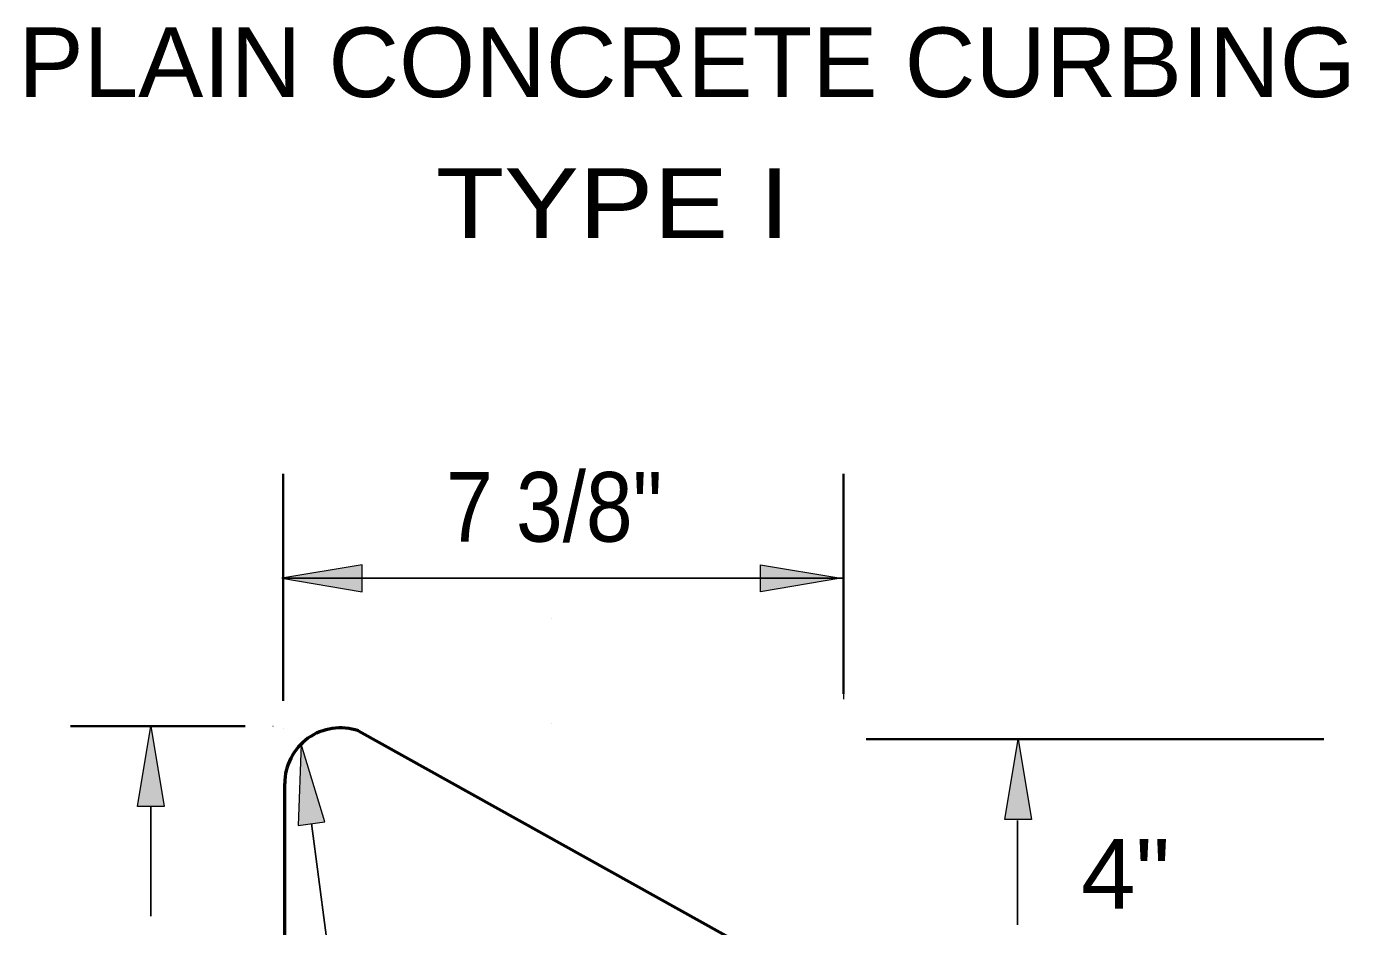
# Model space of a CAD drawing. Extents: x 36.6 to 71.9, y 0.8 to 22.8.
# Drawn here: x 55.33 to 58.293, y 14.457 to 16.476 of the extents above; entities that cross this region are included whole.
import ezdxf

# ---------------------------------------------------------------- set-up
doc = ezdxf.new("R2010")
doc.units = 0
doc.header["$LTSCALE"] = 0.062
for name, color, linetype, lineweight in [('1', 7, 'Continuous', 13), ('3', 7, 'Continuous', 25), ('8', 7, 'Continuous', 13)]:
    doc.layers.add(name, color=color, linetype=linetype, lineweight=lineweight)

msp = doc.modelspace()

# ---------------------------------------------------------------- hatches: boundary and pattern name
at = {"layer": '1'}
for points in [[(56.08267, 15.20792), (56.08267, 15.26792), (55.90258, 15.23792), (55.90258, 15.23792)], [(56.97508, 15.20792), (56.97508, 15.26792), (57.15508, 15.23792), (57.15508, 15.23792)], [(55.63867, 14.72633), (55.57867, 14.72633), (55.60858, 14.90633), (55.60858, 14.90633)], [(57.58267, 14.69683), (57.52267, 14.69683), (57.55267, 14.87683), (57.55267, 14.87683)]]:
    msp.add_hatch(color=256, dxfattribs=at).paths.add_polyline_path(points)
at = {"layer": '3'}
msp.add_hatch(color=256, dxfattribs=at).paths.add_polyline_path([(55.93925, 14.68383), (55.99883, 14.69167), (55.94575, 14.86625), (55.94575, 14.86625)])

# ---------------------------------------------------------------- linework, layer by layer
at = {"layer": '1', "lineweight": 35}
for p, q in [((55.9055, 14.96308), (55.9055, 15.47192)), ((57.16108, 14.97875), (57.16108, 15.47192)), ((55.82008, 14.90633), (55.42867, 14.90633)), ((57.21225, 14.87725), (58.23817, 14.87725))]:
    msp.add_line(p, q, dxfattribs=at)
at = {"layer": '1'}
for p, q in [((55.9055, 15.02558), (55.9055, 15.32692)), ((57.16108, 15.08442), (57.16108, 14.96692))]:
    msp.add_line(p, q, dxfattribs=at)
at = {"layer": '1', "lineweight": 25}
for p, q in [((57.15808, 15.23792), (55.9025, 15.23792)), ((55.60867, 14.48058), (55.60867, 14.72633)), ((57.55117, 14.69517), (57.55117, 14.46067))]:
    msp.add_line(p, q, dxfattribs=at)
at = {"layer": '1', "lineweight": 53}
for p, q in [((56.074, 14.89583), (57.09425, 14.3275)), ((55.90883, 11.51508), (55.90883, 14.7775))]:
    msp.add_line(p, q, dxfattribs=at)
at = {"layer": '1'}
for points in [[(56.08267, 15.20792), (56.08267, 15.26792), (55.90258, 15.23792), (55.90258, 15.23792)], [(56.97508, 15.20792), (56.97508, 15.26792), (57.15508, 15.23792), (57.15508, 15.23792)], [(55.63867, 14.72633), (55.57867, 14.72633), (55.60858, 14.90633), (55.60858, 14.90633)], [(57.58267, 14.69683), (57.52267, 14.69683), (57.55267, 14.87683), (57.55267, 14.87683)]]:
    msp.add_lwpolyline(points, close=True, dxfattribs=at)
at = {"layer": '1', "lineweight": 53}
msp.add_arc((56.03383, 14.7775), 0.125, 71.23187, 180, dxfattribs=at)
at = {"layer": '3', "lineweight": 13}
msp.add_lwpolyline([(55.93925, 14.68383), (55.99883, 14.69167), (55.94575, 14.86625), (55.94575, 14.86625)], close=True, dxfattribs=at)
at = {"layer": '3'}
msp.add_lwpolyline([(55.96908, 14.68775), (56.03158, 14.20958), (56.36908, 13.96008)], dxfattribs=at)
at = {"layer": '8'}
for p, q in [((57.16108, 15.45325), (57.16117, 15.45325)), ((55.9055, 15.14692), (55.90558, 15.14692)), ((56.50625, 15.14692), (56.50633, 15.14692)), ((57.16108, 15.14692), (57.16117, 15.14692)), ((57.16108, 15.14692), (57.16117, 15.14692)), ((55.9055, 14.96308), (55.90558, 14.96308)), ((55.60867, 14.90633), (55.60875, 14.90633)), ((55.88258, 14.90633), (55.88267, 14.90633)), ((56.50625, 14.91258), (56.50633, 14.91258)), ((55.9055, 14.90058), (55.90558, 14.90058))]:
    msp.add_line(p, q, dxfattribs=at)

# ---------------------------------------------------------------- texts
at = {"layer": '1'}
for s, width, p in [('7 3/8"', 0.9, (56.27058, 15.32008)), ('4"', 1.05, (57.69367, 14.49717))]:
    msp.add_text(s, height=0.1562, dxfattribs=dict(at, width=width)).set_placement(p)
at = {"layer": '3'}
for s, width, p in [('PLAIN CONCRETE CURBING', 1.05, (55.312, 16.31708)), ('TYPE I', 1.2, (56.24775, 16.001))]:
    msp.add_text(s, height=0.1562, dxfattribs=dict(at, width=width)).set_placement(p)

doc.saveas('drawing.dxf')
